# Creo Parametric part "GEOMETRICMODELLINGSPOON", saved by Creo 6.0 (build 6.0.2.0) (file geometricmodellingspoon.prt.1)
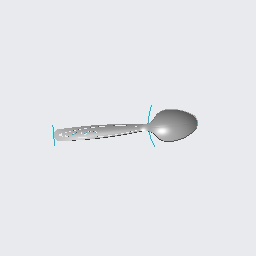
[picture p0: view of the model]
Units: Inch lbm Second (Pro/E Default); INCH, POUND, SECS

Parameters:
  SMT_PART_BEND_ALLOW_FACTOR_TYPE = "Y FACTOR"
  SMT_DFLT_RADIUS_SIDE = "Inside"
  SMT_DFLT_CRNR_REL_TYPE = "V Notch"
  SMT_DFLT_BEND_REL_TYPE = "Rip"
  SMT_DFLT_BEND_REL_DEPTH_TYPE = "Up to Bend"
  SMT_DFLT_EDGE_TREA_TYPE = "Open"
  SMT_DFLT_CRNR_REL_DEPTH_TYPE = "On Origin"
  SMT_DFLT_BEND_REL_LENGTH_TYPE = "Through All"

Other parameters: SMT_THICKNESS, SMT_PART_BEND_ALLOWANCE_FACTOR, SMT_UPDATE_BEND_ALLOW_INFO, SMT_DFLT_BEND_RADIUS, SMT_DFLT_BEND_ANGLE, SMT_DFLT_CRNR_REL_WIDTH, SMT_DFLT_CRNR_REL_DEPTH, SMT_DFLT_BEND_REL_WIDTH, SMT_DFLT_BEND_REL_DEPTH, SMT_DFLT_BEND_REL_ANGLE, SMT_GAP, SMT_DFLT_EDGE_TREA_WIDTH, SMT_DFLT_MITER_CUT_WIDTH, SMT_DFLT_MITER_CUT_OFFSET, SMT_DFLT_BEND_REL_LENGTH, D142, D155, D169, D231, D236, D237, D247, D265, D264, D277, D290, D289, D306

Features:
  1. datum plane "RIGHT"
  2. datum plane "TOP"
  3. datum plane "FRONT"
  4. coordinate system
  5. coordinate system
  6. curve
  7. datum plane "DTM1"
  8. datum plane "DTM2"
  9. datum plane "DTM3"
  10. datum plane "DTM4"
  11. curve
  12. curve
  13. curve
  14. curve
  15. curve "A_1"
  16. curve
  17. sketch "Sketch 9"
  18. extruded cut "Extrude 4"
  19. sketch "Sketch 10"
  20. cut

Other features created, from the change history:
  sketch "Sketch 9" (2 times)
  feature "Extrude 4"

Other named items: CS0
